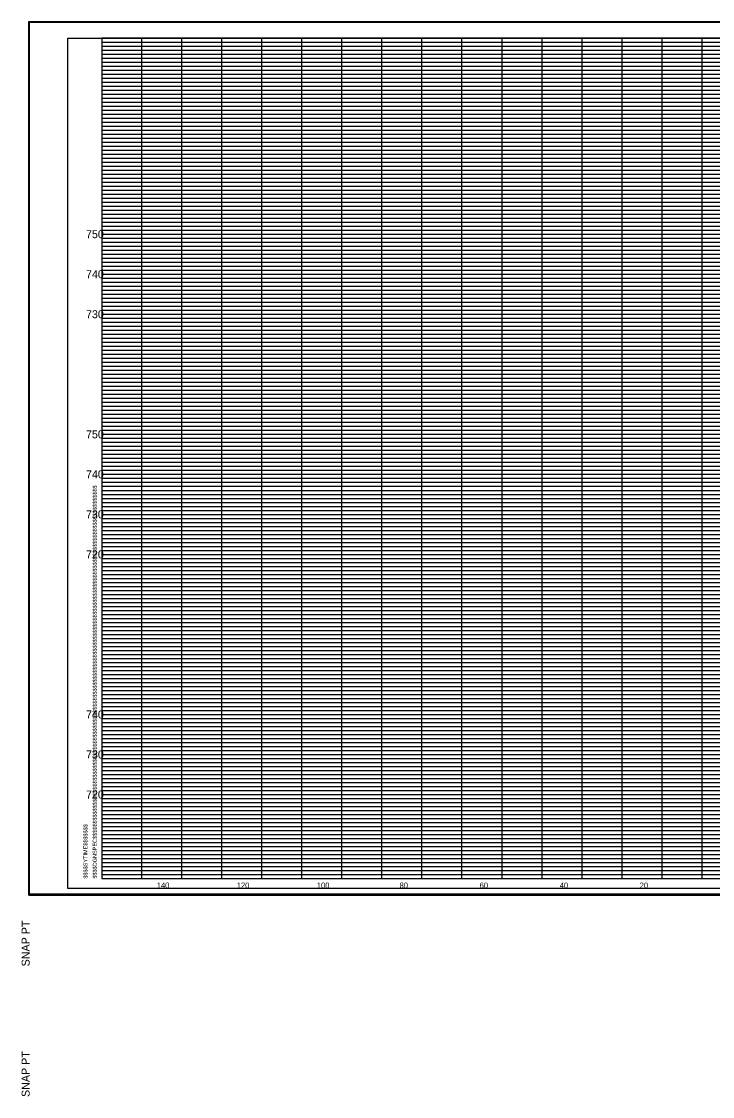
# Model space of a CAD drawing. Extents: x -200 to 1704, y -325 to 2307.
# Drawn here: x 979.9 to 1152.6, y 1755.5 to 2024.1 of the extents above; entities that cross this region are included whole.
import ezdxf

# ---------------------------------------------------------------- set-up
doc = ezdxf.new("R2010")
doc.units = 0
for name, color, linetype in [('DESIGN - SHEET - Corner Text', 7, 'Continuous'), ('DESIGN - SHEET - Light Grid', 7, 'Continuous'), ('DESIGN - SHEET - Linework', 7, 'Continuous'), ('DESIGN - SHEET - Plot Shape', 7, 'Continuous'), ('DESIGN - TYPICAL - Text', 7, 'Continuous')]:
    doc.layers.add(name, color=color, linetype=linetype)

msp = doc.modelspace()

# ---------------------------------------------------------------- linework, layer by layer
at = {"layer": 'DESIGN - SHEET - Light Grid'}
for p, q in [((1000, 2019), (1080, 2019)), ((1000, 2018), (1080, 2018)), ((1080, 2019), (1160, 2019)), ((1080, 2018), (1160, 2018)), ((1000, 2017), (1080, 2017)), ((1000, 2016), (1080, 2016)), ((1000, 2015), (1080, 2015)), ((1080, 2017), (1160, 2017)), ((1080, 2016), (1160, 2016)), ((1080, 2015), (1160, 2015)), ((1000, 2014), (1080, 2014)), ((1000, 2013), (1080, 2013)), ((1000, 2012), (1080, 2012)), ((1080, 2014), (1160, 2014)), ((1080, 2013), (1160, 2013)), ((1080, 2012), (1160, 2012)), ((1000, 2011), (1080, 2011)), ((1080, 2011), (1160, 2011)), ((1000, 2009), (1080, 2009)), ((1000, 2008), (1080, 2008)), ((1000, 2007), (1080, 2007)), ((1080, 2009), (1160, 2009)), ((1080, 2008), (1160, 2008)), ((1080, 2007), (1160, 2007)), ((1000, 2006), (1080, 2006)), ((1000, 2005), (1080, 2005)), ((1000, 2004), (1080, 2004)), ((1080, 2006), (1160, 2006)), ((1080, 2005), (1160, 2005)), ((1080, 2004), (1160, 2004)), ((1000, 2003), (1080, 2003)), ((1000, 2002), (1080, 2002)), ((1080, 2003), (1160, 2003)), ((1080, 2002), (1160, 2002)), ((1000, 2001), (1080, 2001)), ((1000, 1999), (1080, 1999)), ((1080, 2001), (1160, 2001)), ((1080, 1999), (1160, 1999)), ((1000, 1998), (1080, 1998)), ((1000, 1997), (1080, 1997)), ((1000, 1996), (1080, 1996)), ((1080, 1998), (1160, 1998)), ((1080, 1997), (1160, 1997)), ((1080, 1996), (1160, 1996)), ((1000, 1995), (1080, 1995)), ((1000, 1994), (1080, 1994)), ((1000, 1993), (1080, 1993)), ((1080, 1995), (1160, 1995)), ((1080, 1994), (1160, 1994)), ((1080, 1993), (1160, 1993)), ((1000, 1992), (1080, 1992)), ((1000, 1991), (1080, 1991)), ((1080, 1992), (1160, 1992)), ((1080, 1991), (1160, 1991)), ((1000, 1989), (1080, 1989)), ((1000, 1988), (1080, 1988)), ((1080, 1989), (1160, 1989)), ((1080, 1988), (1160, 1988)), ((1000, 1987), (1080, 1987)), ((1000, 1986), (1080, 1986)), ((1000, 1985), (1080, 1985)), ((1080, 1987), (1160, 1987)), ((1080, 1986), (1160, 1986)), ((1080, 1985), (1160, 1985)), ((1000, 1984), (1080, 1984)), ((1000, 1983), (1080, 1983)), ((1080, 1984), (1160, 1984)), ((1080, 1983), (1160, 1983)), ((1000, 1982), (1080, 1982)), ((1000, 1981), (1080, 1981)), ((1080, 1982), (1160, 1982)), ((1080, 1981), (1160, 1981)), ((1000, 1979), (1080, 1979)), ((1000, 1978), (1080, 1978)), ((1000, 1977), (1080, 1977)), ((1080, 1979), (1160, 1979)), ((1080, 1978), (1160, 1978)), ((1080, 1977), (1160, 1977)), ((1000, 1976), (1080, 1976)), ((1000, 1975), (1080, 1975)), ((1080, 1976), (1160, 1976)), ((1080, 1975), (1160, 1975)), ((1000, 1974), (1080, 1974)), ((1000, 1973), (1080, 1973)), ((1000, 1972), (1080, 1972)), ((1080, 1974), (1160, 1974)), ((1080, 1973), (1160, 1973)), ((1080, 1972), (1160, 1972)), ((1000, 1971), (1080, 1971)), ((1000, 1969), (1080, 1969)), ((1080, 1971), (1160, 1971)), ((1080, 1969), (1160, 1969)), ((1000, 1968), (1080, 1968)), ((1000, 1967), (1080, 1967)), ((1080, 1968), (1160, 1968)), ((1080, 1967), (1160, 1967)), ((1000, 1966), (1080, 1966)), ((1000, 1965), (1080, 1965)), ((1000, 1964), (1080, 1964)), ((1080, 1966), (1160, 1966)), ((1080, 1965), (1160, 1965)), ((1080, 1964), (1160, 1964)), ((1000, 1963), (1080, 1963)), ((1000, 1962), (1080, 1962)), ((1000, 1961), (1080, 1961)), ((1080, 1963), (1160, 1963)), ((1080, 1962), (1160, 1962)), ((1080, 1961), (1160, 1961)), ((1000, 1959), (1080, 1959)), ((1080, 1959), (1160, 1959)), ((1000, 1958), (1080, 1958)), ((1000, 1957), (1080, 1957)), ((1000, 1956), (1080, 1956)), ((1080, 1958), (1160, 1958)), ((1080, 1957), (1160, 1957)), ((1080, 1956), (1160, 1956)), ((1000, 1955), (1080, 1955)), ((1000, 1954), (1080, 1954)), ((1000, 1953), (1080, 1953)), ((1080, 1955), (1160, 1955)), ((1080, 1954), (1160, 1954)), ((1080, 1953), (1160, 1953)), ((1000, 1952), (1080, 1952)), ((1000, 1951), (1080, 1951)), ((1080, 1952), (1160, 1952)), ((1080, 1951), (1160, 1951)), ((1000, 1949), (1080, 1949)), ((1000, 1948), (1080, 1948)), ((1080, 1949), (1160, 1949)), ((1080, 1948), (1160, 1948)), ((1000, 1947), (1080, 1947)), ((1000, 1946), (1080, 1946)), ((1000, 1945), (1080, 1945)), ((1080, 1947), (1160, 1947)), ((1080, 1946), (1160, 1946)), ((1080, 1945), (1160, 1945)), ((1000, 1944), (1080, 1944)), ((1000, 1943), (1080, 1943)), ((1000, 1942), (1080, 1942)), ((1080, 1944), (1160, 1944)), ((1080, 1943), (1160, 1943)), ((1080, 1942), (1160, 1942)), ((1000, 1941), (1080, 1941)), ((1080, 1941), (1160, 1941)), ((1000, 1939), (1080, 1939)), ((1000, 1938), (1080, 1938)), ((1000, 1937), (1080, 1937)), ((1080, 1939), (1160, 1939)), ((1080, 1938), (1160, 1938)), ((1080, 1937), (1160, 1937)), ((1000, 1936), (1080, 1936)), ((1000, 1935), (1080, 1935)), ((1000, 1934), (1080, 1934)), ((1080, 1936), (1160, 1936)), ((1080, 1935), (1160, 1935)), ((1080, 1934), (1160, 1934)), ((1000, 1933), (1080, 1933)), ((1000, 1932), (1080, 1932)), ((1080, 1933), (1160, 1933)), ((1080, 1932), (1160, 1932)), ((1000, 1931), (1080, 1931)), ((1000, 1929), (1080, 1929)), ((1080, 1931), (1160, 1931)), ((1080, 1929), (1160, 1929)), ((1000, 1928), (1080, 1928)), ((1000, 1927), (1080, 1927)), ((1000, 1926), (1080, 1926)), ((1080, 1928), (1160, 1928)), ((1080, 1927), (1160, 1927)), ((1080, 1926), (1160, 1926)), ((1000, 1925), (1080, 1925)), ((1000, 1924), (1080, 1924)), ((1080, 1925), (1160, 1925)), ((1080, 1924), (1160, 1924)), ((1000, 1923), (1080, 1923)), ((1000, 1922), (1080, 1922)), ((1000, 1921), (1080, 1921)), ((1080, 1923), (1160, 1923)), ((1080, 1922), (1160, 1922)), ((1080, 1921), (1160, 1921)), ((1000, 1919), (1080, 1919)), ((1000, 1918), (1080, 1918)), ((1080, 1919), (1160, 1919)), ((1080, 1918), (1160, 1918)), ((1000, 1917), (1080, 1917)), ((1000, 1916), (1080, 1916)), ((1080, 1917), (1160, 1917)), ((1080, 1916), (1160, 1916)), ((1000, 1915), (1080, 1915)), ((1000, 1914), (1080, 1914)), ((1000, 1913), (1080, 1913)), ((1080, 1915), (1160, 1915)), ((1080, 1914), (1160, 1914)), ((1080, 1913), (1160, 1913)), ((1000, 1912), (1080, 1912)), ((1000, 1911), (1080, 1911)), ((1080, 1912), (1160, 1912)), ((1080, 1911), (1160, 1911)), ((1000, 1909), (1080, 1909)), ((1000, 1908), (1080, 1908)), ((1080, 1909), (1160, 1909)), ((1080, 1908), (1160, 1908)), ((1000, 1907), (1080, 1907)), ((1000, 1906), (1080, 1906)), ((1000, 1905), (1080, 1905)), ((1080, 1907), (1160, 1907)), ((1080, 1906), (1160, 1906)), ((1080, 1905), (1160, 1905)), ((1000, 1904), (1080, 1904)), ((1000, 1903), (1080, 1903)), ((1000, 1902), (1080, 1902)), ((1080, 1904), (1160, 1904)), ((1080, 1903), (1160, 1903)), ((1080, 1902), (1160, 1902)), ((1000, 1901), (1080, 1901)), ((1000, 1899), (1080, 1899)), ((1080, 1901), (1160, 1901)), ((1080, 1899), (1160, 1899)), ((1000, 1898), (1080, 1898)), ((1000, 1897), (1080, 1897)), ((1080, 1898), (1160, 1898)), ((1080, 1897), (1160, 1897)), ((1000, 1896), (1080, 1896)), ((1000, 1895), (1080, 1895)), ((1000, 1894), (1080, 1894)), ((1080, 1896), (1160, 1896)), ((1080, 1895), (1160, 1895)), ((1080, 1894), (1160, 1894)), ((1000, 1893), (1080, 1893)), ((1000, 1892), (1080, 1892)), ((1000, 1891), (1080, 1891)), ((1080, 1893), (1160, 1893)), ((1080, 1892), (1160, 1892)), ((1080, 1891), (1160, 1891)), ((1000, 1889), (1080, 1889)), ((1080, 1889), (1160, 1889)), ((1000, 1888), (1080, 1888)), ((1000, 1887), (1080, 1887)), ((1000, 1886), (1080, 1886)), ((1080, 1888), (1160, 1888)), ((1080, 1887), (1160, 1887)), ((1080, 1886), (1160, 1886)), ((1000, 1885), (1080, 1885)), ((1000, 1884), (1080, 1884)), ((1000, 1883), (1080, 1883)), ((1080, 1885), (1160, 1885)), ((1080, 1884), (1160, 1884)), ((1080, 1883), (1160, 1883)), ((1000, 1882), (1080, 1882)), ((1000, 1881), (1080, 1881)), ((1080, 1882), (1160, 1882)), ((1080, 1881), (1160, 1881)), ((1000, 1879), (1080, 1879)), ((1000, 1878), (1080, 1878)), ((1080, 1879), (1160, 1879)), ((1080, 1878), (1160, 1878)), ((1000, 1877), (1080, 1877)), ((1000, 1876), (1080, 1876)), ((1000, 1875), (1080, 1875)), ((1080, 1877), (1160, 1877)), ((1080, 1876), (1160, 1876)), ((1080, 1875), (1160, 1875)), ((1000, 1874), (1080, 1874)), ((1000, 1873), (1080, 1873)), ((1080, 1874), (1160, 1874)), ((1080, 1873), (1160, 1873)), ((1000, 1872), (1080, 1872)), ((1000, 1871), (1080, 1871)), ((1080, 1872), (1160, 1872)), ((1080, 1871), (1160, 1871)), ((1000, 1869), (1080, 1869)), ((1000, 1868), (1080, 1868)), ((1000, 1867), (1080, 1867)), ((1080, 1869), (1160, 1869)), ((1080, 1868), (1160, 1868)), ((1080, 1867), (1160, 1867)), ((1000, 1866), (1080, 1866)), ((1000, 1865), (1080, 1865)), ((1080, 1866), (1160, 1866)), ((1080, 1865), (1160, 1865)), ((1000, 1864), (1080, 1864)), ((1000, 1863), (1080, 1863)), ((1000, 1862), (1080, 1862)), ((1080, 1864), (1160, 1864)), ((1080, 1863), (1160, 1863)), ((1080, 1862), (1160, 1862)), ((1000, 1861), (1080, 1861)), ((1000, 1859), (1080, 1859)), ((1080, 1861), (1160, 1861)), ((1080, 1859), (1160, 1859)), ((1000, 1858), (1080, 1858)), ((1000, 1857), (1080, 1857)), ((1000, 1856), (1080, 1856)), ((1080, 1858), (1160, 1858)), ((1080, 1857), (1160, 1857)), ((1080, 1856), (1160, 1856)), ((1000, 1855), (1080, 1855)), ((1000, 1854), (1080, 1854)), ((1080, 1855), (1160, 1855)), ((1080, 1854), (1160, 1854)), ((1000, 1853), (1080, 1853)), ((1000, 1852), (1080, 1852)), ((1000, 1851), (1080, 1851)), ((1080, 1853), (1160, 1853)), ((1080, 1852), (1160, 1852)), ((1080, 1851), (1160, 1851)), ((1000, 1849), (1080, 1849)), ((1000, 1848), (1080, 1848)), ((1080, 1849), (1160, 1849)), ((1080, 1848), (1160, 1848)), ((1000, 1847), (1080, 1847)), ((1000, 1846), (1080, 1846)), ((1080, 1847), (1160, 1847)), ((1080, 1846), (1160, 1846)), ((1000, 1845), (1080, 1845)), ((1000, 1844), (1080, 1844)), ((1000, 1843), (1080, 1843)), ((1080, 1845), (1160, 1845)), ((1080, 1844), (1160, 1844)), ((1080, 1843), (1160, 1843)), ((1000, 1842), (1080, 1842)), ((1000, 1841), (1080, 1841)), ((1080, 1842), (1160, 1842)), ((1080, 1841), (1160, 1841)), ((1000, 1839), (1080, 1839)), ((1000, 1838), (1080, 1838)), ((1080, 1839), (1160, 1839)), ((1080, 1838), (1160, 1838)), ((1000, 1837), (1080, 1837)), ((1000, 1836), (1080, 1836)), ((1000, 1835), (1080, 1835)), ((1080, 1837), (1160, 1837)), ((1080, 1836), (1160, 1836)), ((1080, 1835), (1160, 1835)), ((1000, 1834), (1080, 1834)), ((1000, 1833), (1080, 1833)), ((1000, 1832), (1080, 1832)), ((1080, 1834), (1160, 1834)), ((1080, 1833), (1160, 1833)), ((1080, 1832), (1160, 1832)), ((1000, 1831), (1080, 1831)), ((1080, 1831), (1160, 1831)), ((1000, 1829), (1080, 1829)), ((1000, 1828), (1080, 1828)), ((1000, 1827), (1080, 1827)), ((1080, 1829), (1160, 1829)), ((1080, 1828), (1160, 1828)), ((1080, 1827), (1160, 1827)), ((1000, 1826), (1080, 1826)), ((1000, 1825), (1080, 1825)), ((1000, 1824), (1080, 1824)), ((1080, 1826), (1160, 1826)), ((1080, 1825), (1160, 1825)), ((1080, 1824), (1160, 1824)), ((1000, 1823), (1080, 1823)), ((1000, 1822), (1080, 1822)), ((1080, 1823), (1160, 1823)), ((1080, 1822), (1160, 1822)), ((1000, 1821), (1080, 1821)), ((1000, 1819), (1080, 1819)), ((1080, 1821), (1160, 1821)), ((1080, 1819), (1160, 1819)), ((1000, 1818), (1080, 1818)), ((1000, 1817), (1080, 1817)), ((1000, 1816), (1080, 1816)), ((1080, 1818), (1160, 1818)), ((1080, 1817), (1160, 1817)), ((1080, 1816), (1160, 1816)), ((1000, 1815), (1080, 1815)), ((1000, 1814), (1080, 1814)), ((1000, 1813), (1080, 1813)), ((1080, 1815), (1160, 1815)), ((1080, 1814), (1160, 1814)), ((1080, 1813), (1160, 1813)), ((1000, 1812), (1080, 1812)), ((1000, 1811), (1080, 1811)), ((1080, 1812), (1160, 1812)), ((1080, 1811), (1160, 1811))]:
    msp.add_line(p, q, dxfattribs=at)
at = {"layer": 'DESIGN - SHEET - Linework'}
for p, q in [((981.77, 1805.86), (981.77, 2024.14)), ((981.77, 2024.14), (1322.17, 2024.14)), ((1010, 1810), (1010, 2020)), ((1020, 1810), (1020, 2020)), ((1030, 1810), (1030, 2020)), ((1040, 1810), (1040, 2020)), ((1050, 1810), (1050, 2020)), ((1060, 1810), (1060, 2020)), ((1070, 1810), (1070, 2020)), ((1080, 1810), (1080, 2020)), ((1090, 1810), (1090, 2020)), ((1100, 1810), (1100, 2020)), ((1110, 1810), (1110, 2020)), ((1120, 1810), (1120, 2020)), ((1130, 1810), (1130, 2020)), ((1140, 1810), (1140, 2020)), ((1150, 1810), (1150, 2020)), ((1000, 2010), (1280, 2010)), ((1000, 2000), (1320, 2000)), ((1000, 1990), (1320, 1990)), ((1000, 1980), (1320, 1980)), ((1000, 1970), (1320, 1970)), ((1000, 1960), (1320, 1960)), ((1000, 1950), (1320, 1950)), ((1000, 1940), (1320, 1940)), ((1000, 1930), (1320, 1930)), ((1000, 1920), (1320, 1920)), ((1000, 1910), (1320, 1910)), ((1000, 1900), (1320, 1900)), ((1000, 1890), (1320, 1890)), ((1000, 1880), (1320, 1880)), ((1000, 1870), (1320, 1870)), ((1000, 1860), (1320, 1860)), ((1000, 1850), (1320, 1850)), ((1000, 1840), (1320, 1840)), ((1000, 1830), (1320, 1830)), ((1000, 1820), (1320, 1820)), ((981.77, 1805.86), (1322.17, 1805.86))]:
    msp.add_line(p, q, dxfattribs=at)
msp.add_lwpolyline([(1000, 2020), (1000, 1810), (1320, 1810), (1320, 2020), (1000, 2020)], dxfattribs=at)
at = {"layer": 'DESIGN - SHEET - Plot Shape'}
for points in [[(981.97, 2023.94), (1321.97, 2023.94), (1321.97, 1806.06), (981.97, 1806.06)], [(991.5, 2020), (1320, 2020), (1320, 1807.5), (991.5, 1807.5)]]:
    msp.add_lwpolyline(points, close=True, dxfattribs=at)

# ---------------------------------------------------------------- texts
at = {"layer": 'DESIGN - SHEET - Corner Text'}
for s, height, p in [('$$$$DGNSPEC$$$$$$$$$$$$$$$$$$$$$$$$$$$$$$$$$$$$$$$$$$$$$$$$$$$$$$$$$$$$$$$$$$$$$$$$$$$$$$$$$$$$$$$$$$$$$$$$$$$$$$$$$$$$$$$$$$$', 1.00002, (998.74, 1810)), ('$$$$SYTIME$$$$$$$', 1, (996.42, 1810)), ('SNAP PT  ', 2, (981.97, 1788.06)), ('  SNAP PT', 2, (981.97, 1753.94))]:
    msp.add_text(s, height=height, rotation=90, dxfattribs=at).set_placement(p)
at = {"layer": 'DESIGN - TYPICAL - Text'}
for s, height, p in [('     750     ', 2, (992.34, 1970)), ('     740     ', 2, (992.34, 1960)), ('     730     ', 2, (992.34, 1950)), ('     750     ', 2, (992.34, 1920)), ('     740     ', 2, (992.34, 1910)), ('     730     ', 2, (992.34, 1900)), ('     720     ', 2, (992.34, 1890)), ('     740     ', 2, (992.34, 1850)), ('     730     ', 2, (992.34, 1840)), ('     720     ', 2, (992.34, 1830)), ('     140     ', 1.4, (1011.14, 1807.6)), ('     120     ', 1.4, (1031.14, 1807.6)), ('     100     ', 1.4, (1051.14, 1807.6)), ('     80     ', 1.4, (1071.82, 1807.6)), ('     60     ', 1.4, (1091.82, 1807.6)), ('     40     ', 1.4, (1111.82, 1807.6)), ('     20     ', 1.4, (1131.82, 1807.6))]:
    msp.add_text(s, height=height, dxfattribs=at).set_placement(p)

doc.saveas('drawing.dxf')
